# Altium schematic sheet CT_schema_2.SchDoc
size 276 x 169 mm
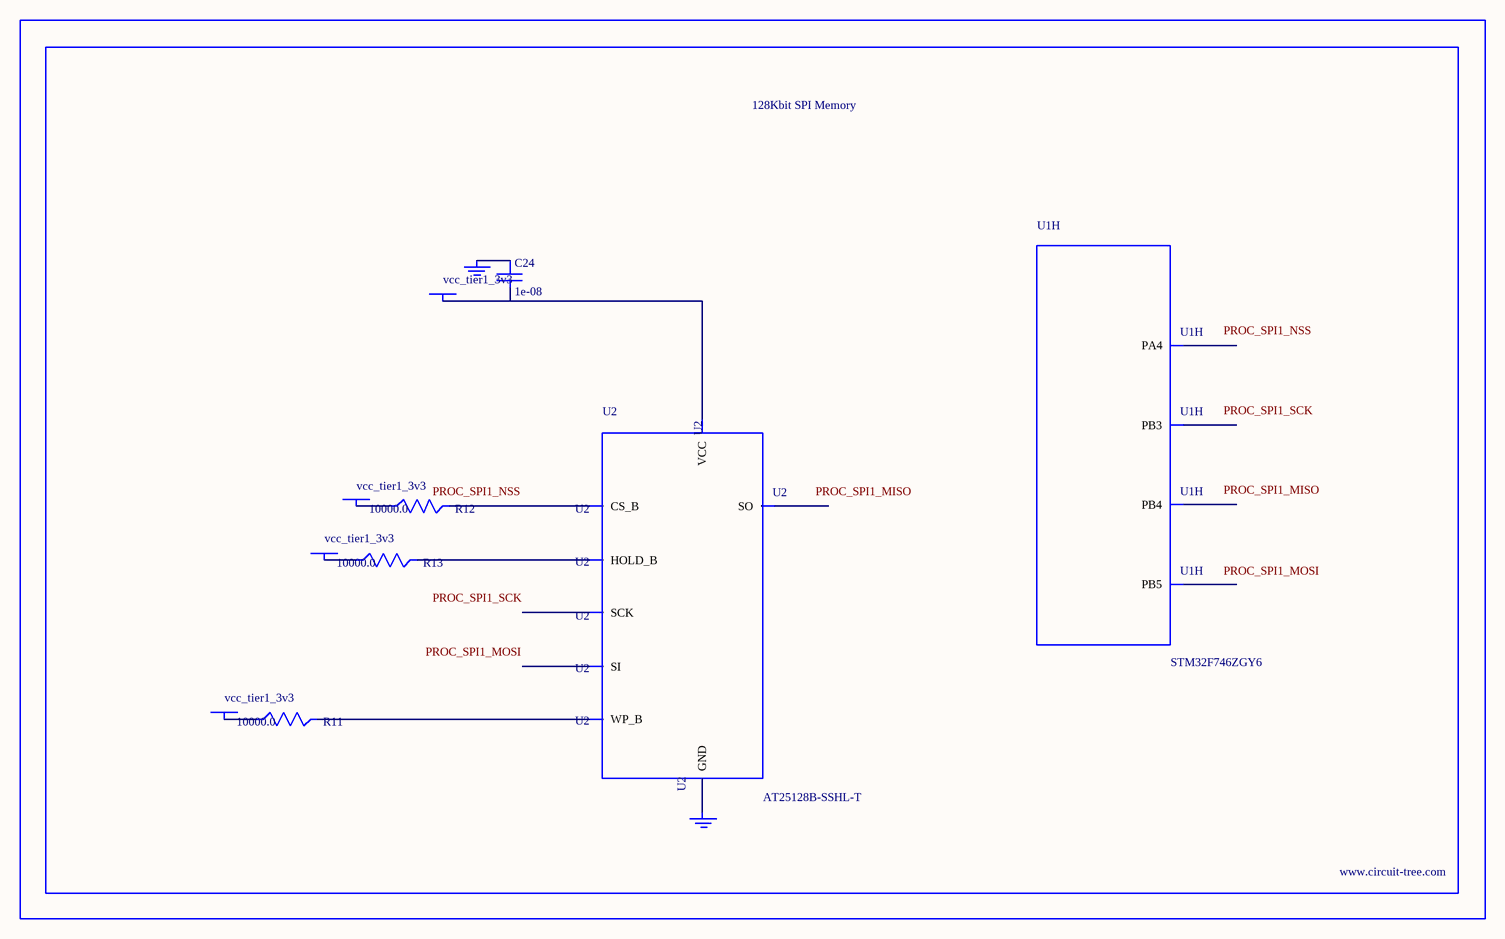
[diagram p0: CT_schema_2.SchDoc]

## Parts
BORDER1  (no value)
C24  1e-08  [C0402]
GND_INSTANCE_1_0  (no value)
GND_INSTANCE_1_1  (no value)
POWER_INSTANCE_1_0  vcc_tier1_3v3
POWER_INSTANCE_1_1  vcc_tier1_3v3
POWER_INSTANCE_1_2  vcc_tier1_3v3
POWER_INSTANCE_1_3  vcc_tier1_3v3
R11  10000.0  [R0603]
R12  10000.0  [R0603]
R13  10000.0  [R0603]
U1  STM32F746ZGY6  [WLCSP143]  (part H of 13)
U2  AT25128B-SSHL-T  [SOIC-8]

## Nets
NetC24_1: C24.1 GND_INSTANCE_1_0.0(GND)
NetC24_2: C24.2 POWER_INSTANCE_1_3.0(PWR) U2.8(VCC)
NetGND_INSTANCE_1_1_0: GND_INSTANCE_1_1.0(GND) U2.4(GND)
NetPOWER_INSTANCE_1_0_0: POWER_INSTANCE_1_0.0(PWR) R12.1
NetPOWER_INSTANCE_1_1_0: POWER_INSTANCE_1_1.0(PWR) R11.1
NetPOWER_INSTANCE_1_2_0: POWER_INSTANCE_1_2.0(PWR) R13.1
NetR11_2: R11.2 U2.3(WP_B)
NetR12_2: R12.2 U2.1(CS_B)
NetR13_2: R13.2 U2.7(HOLD_B)

Not connected (* = marked no-connect by the designer): U1 B7(PB3) C7(PB4) C8(PB5) M10(PA4); U2 2(SO) 5(SI) 6(SCK)

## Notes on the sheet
- Labels drawn without touching a wire or pin: PROC_SPI1_MISO, PROC_SPI1_MOSI, PROC_SPI1_NSS, PROC_SPI1_SCK

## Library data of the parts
BORDER1 = BORDER_PAGE1
C24 = C0402C103K3RAC
GND_INSTANCE_1_0 GND_INSTANCE_1_1 = GND
POWER_INSTANCE_1_0-POWER_INSTANCE_1_3 = PWR
R11-R13 = RC0603JR-0710KL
